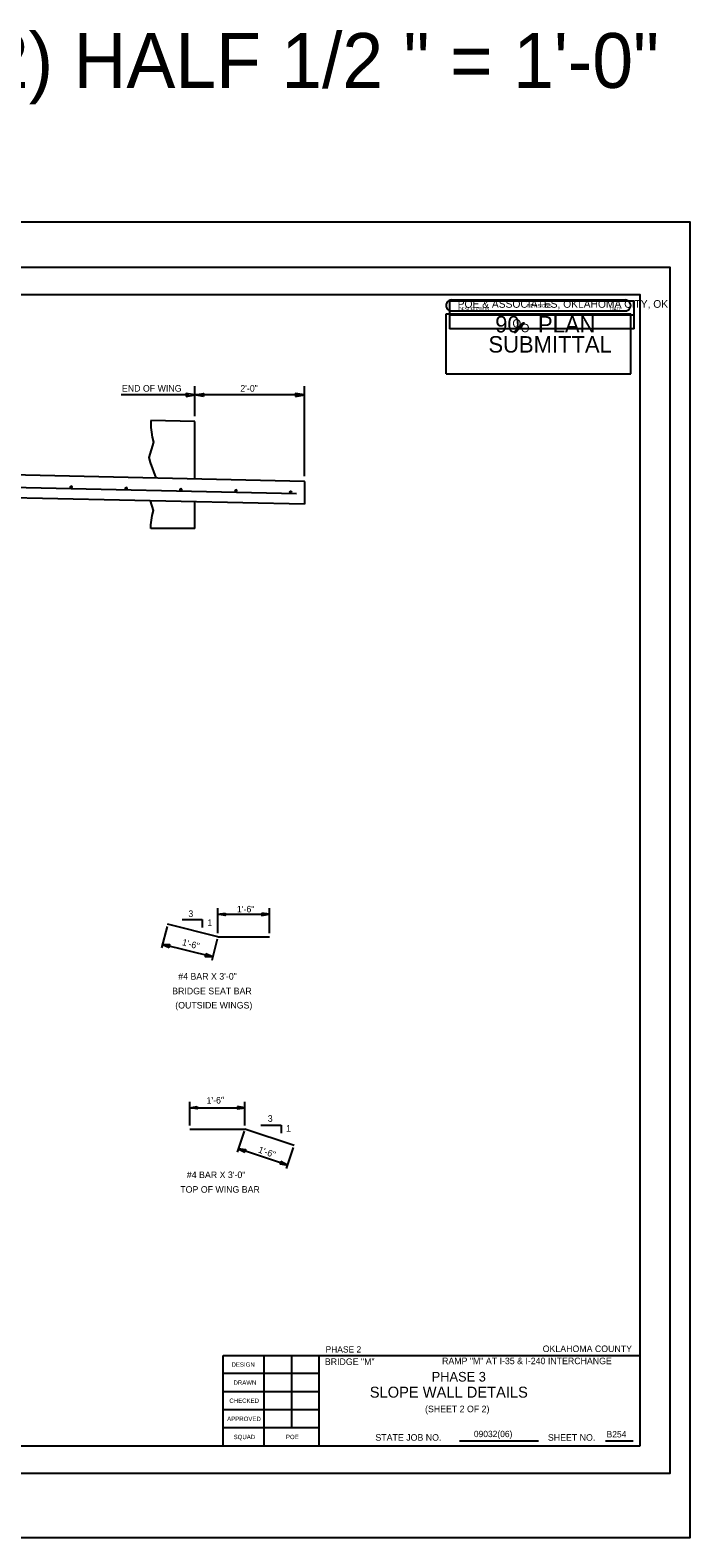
# Model space of a CAD drawing. Extents: x 570 to 2153298, y 726 to 139926.
# Drawn here: x 2153165.19 to 2153177.23, y 139597.62 to 139625.12 of the extents above; entities that cross this region are included whole.
import ezdxf

# ---------------------------------------------------------------- set-up
doc = ezdxf.new("R2010")
doc.units = 0
for name, color, linetype in [('4', 7, 'Continuous'), ('6', 7, 'Continuous'), ('Default', 7, 'Continuous'), ('PR_Bridge_Prof', 7, 'Continuous'), ('PR_Dimensions', 7, 'Continuous'), ('PR_JOINT', 7, 'Continuous'), ('PR_Reinforcing', 7, 'Continuous'), ('PR_SlopeWall', 7, 'Continuous'), ('S', 7, 'Continuous'), ('SHT_Plot_Shape_Full', 7, 'Continuous'), ('SHT_Plot_Shape_Half', 7, 'Continuous'), ('SHT_Sheet_Border', 7, 'Continuous'), ('SHT_Stamp_90_Submit', 7, 'Continuous'), ('SHT_Stamp_Rev_Block', 7, 'Continuous'), ('SHT_Standard_Sheet_Lines', 7, 'Continuous'), ('SHT_Standard_Sheet_Txt', 7, 'Continuous'), ('T', 7, 'Continuous'), ('T-Title', 7, 'Continuous')]:
    doc.layers.add(name, color=color, linetype=linetype)

# ---------------------------------------------------------------- blocks, each defined once
blk = doc.blocks.new('ARROWHD_15')
at = {"layer": 'Default'}
blk.add_lwpolyline([(0.0261, -0.0045), (0.0261, 0.0043), (-0.0004, -0.0001)], close=True, dxfattribs=at)

msp = doc.modelspace()

# ---------------------------------------------------------------- linework, layer by layer
at = {"layer": '4'}
for p, q in [((2153168.613, 139608.583), (2153167.699, 139608.813)), ((2153168.613, 139608.583), (2153169.555, 139608.583)), ((2153168.102, 139605.078), (2153169.111, 139605.078)), ((2153170.005, 139604.78), (2153169.111, 139605.078))]:
    msp.add_line(p, q, dxfattribs=at)
at = {"layer": '6'}
for p, q in [((2153168.196, 139618.079), (2153168.196, 139618.623)), ((2153170.195, 139616.986), (2153170.195, 139618.623)), ((2153168.084, 139618.465), (2153166.85, 139618.465)), ((2153170.195, 139618.465), (2153168.196, 139618.465)), ((2153168.613, 139608.65), (2153168.613, 139609.103)), ((2153168.613, 139608.995), (2153169.555, 139608.995)), ((2153169.555, 139608.65), (2153169.555, 139609.103)), ((2153167.689, 139608.773), (2153167.59, 139608.381)), ((2153167.962, 139608.896), (2153168.328, 139608.896)), ((2153168.328, 139608.896), (2153168.328, 139608.751)), ((2153168.52, 139608.216), (2153167.607, 139608.446)), ((2153168.603, 139608.543), (2153168.504, 139608.15)), ((2153168.102, 139605.145), (2153168.102, 139605.574)), ((2153168.102, 139605.466), (2153169.111, 139605.466)), ((2153169.111, 139605.145), (2153169.111, 139605.574)), ((2153169.402, 139605.147), (2153169.768, 139605.147)), ((2153169.768, 139605.147), (2153169.768, 139605.002)), ((2153169.098, 139605.039), (2153168.97, 139604.655)), ((2153169.885, 139604.421), (2153168.991, 139604.719)), ((2153169.992, 139604.741), (2153169.864, 139604.357))]:
    msp.add_line(p, q, dxfattribs=at)
for points in [[(2153168.036, 139618.439), (2153168.196, 139618.465), (2153168.036, 139618.492)], [(2153168.356, 139618.439), (2153168.196, 139618.465), (2153168.356, 139618.492)], [(2153170.035, 139618.439), (2153170.195, 139618.465), (2153170.035, 139618.492)], [(2153168.751, 139609.017), (2153168.751, 139608.972), (2153168.616, 139608.995)], [(2153169.416, 139609.017), (2153169.416, 139608.972), (2153169.551, 139608.995)], [(2153168.241, 139605.489), (2153168.241, 139605.444), (2153168.106, 139605.466)], [(2153168.973, 139605.489), (2153168.973, 139605.444), (2153169.107, 139605.466)]]:
    msp.add_lwpolyline(points, close=True, dxfattribs=at)
at = {"layer": 'PR_Bridge_Prof'}
for p, q in [((2153168.199, 139617.981), (2153167.394, 139617.999)), ((2153168.199, 139616.933), (2153168.199, 139617.981)), ((2153168.199, 139616.028), (2153168.199, 139616.516)), ((2153168.199, 139616.028), (2153167.391, 139616.027))]:
    msp.add_line(p, q, dxfattribs=at)
at = {"layer": 'PR_Dimensions'}
msp.add_line((2153170.198, 139616.888), (2153170.203, 139616.888), dxfattribs=at)
at = {"layer": 'PR_JOINT'}
for points in [[(2153167.394, 139617.999), (2153167.391, 139617.953), (2153167.394, 139617.87), (2153167.404, 139617.784), (2153167.419, 139617.696), (2153167.44, 139617.606), (2153167.357, 139617.323), (2153167.384, 139617.235), (2153167.482, 139616.951)], [(2153167.391, 139616.027), (2153167.394, 139616.094), (2153167.404, 139616.18), (2153167.419, 139616.268), (2153167.44, 139616.358), (2153167.388, 139616.537)]]:
    msp.add_lwpolyline(points, dxfattribs=at)
at = {"layer": 'PR_Reinforcing'}
msp.add_line((2153170.053, 139616.659), (2153162.812, 139616.822), dxfattribs=at)
for centre in [(2153165.941, 139616.785), (2153166.944, 139616.761), (2153167.941, 139616.738), (2153168.945, 139616.718), (2153169.943, 139616.693)]:
    msp.add_circle(centre, 0.0143, dxfattribs=at)
for centre, start, end in [((2153165.941, 139616.785), 356.6255, 176.6255), ((2153165.941, 139616.785), 176.6255, 356.6255), ((2153166.944, 139616.761), 356.6255, 176.6255), ((2153166.944, 139616.761), 176.6255, 356.6255), ((2153167.941, 139616.738), 356.6255, 176.6255), ((2153167.941, 139616.738), 176.6255, 356.6255), ((2153168.945, 139616.718), 356.6255, 176.6255), ((2153168.945, 139616.718), 176.6255, 356.6255), ((2153169.943, 139616.693), 356.6255, 176.6255), ((2153169.943, 139616.693), 176.6255, 356.6255)]:
    msp.add_arc(centre, 0.0143, start, end, dxfattribs=at)
at = {"layer": 'PR_SlopeWall'}
for p, q in [((2153170.198, 139616.888), (2153162.823, 139617.054)), ((2153170.198, 139616.471), (2153162.834, 139616.637)), ((2153170.198, 139616.888), (2153170.198, 139616.471))]:
    msp.add_line(p, q, dxfattribs=at)
at = {"layer": 'SHT_Plot_Shape_Full'}
msp.add_lwpolyline([(2153141.225, 139621.622), (2153177.225, 139621.622), (2153177.225, 139597.622), (2153141.225, 139597.622)], close=True, dxfattribs=at)
at = {"layer": 'SHT_Plot_Shape_Half'}
msp.add_lwpolyline([(2153142.863, 139620.797), (2153176.863, 139620.797), (2153176.863, 139598.797), (2153142.863, 139598.797)], close=True, dxfattribs=at)
at = {"layer": 'SHT_Sheet_Border'}
for p, q in [((2153168.713, 139599.297), (2153168.713, 139600.947)), ((2153168.713, 139600.947), (2153176.313, 139600.947)), ((2153170.463, 139599.297), (2153170.463, 139600.948))]:
    msp.add_line(p, q, dxfattribs=at)
msp.add_lwpolyline([(2153176.313, 139599.297), (2153144.813, 139599.297), (2153144.813, 139620.297), (2153176.313, 139620.297)], close=True, dxfattribs=at)
at = {"layer": 'SHT_Stamp_90_Submit'}
for p, q in [((2153172.78, 139619.947), (2153176.146, 139619.947)), ((2153172.78, 139618.848), (2153172.78, 139619.947)), ((2153172.88, 139620.197), (2153176.046, 139620.197)), ((2153172.88, 139619.997), (2153176.046, 139619.997)), ((2153176.146, 139618.848), (2153176.146, 139619.947)), ((2153174.023, 139619.609), (2153174.179, 139619.781)), ((2153174.041, 139619.609), (2153174.197, 139619.781)), ((2153174.046, 139619.609), (2153174.202, 139619.781)), ((2153174.054, 139619.609), (2153174.209, 139619.781)), ((2153174.179, 139619.781), (2153174.209, 139619.781)), ((2153174.023, 139619.609), (2153174.054, 139619.609)), ((2153172.78, 139618.848), (2153176.146, 139618.848))]:
    msp.add_line(p, q, dxfattribs=at)
for centre, start, end in [((2153172.88, 139620.097), 89.9952, 270), ((2153176.046, 139620.097), 270, 90.0048)]:
    msp.add_arc(centre, 0.1, start, end, dxfattribs=at)
at = {"layer": 'SHT_Stamp_Rev_Block'}
for p, q in [((2153172.844, 139620.173), (2153172.844, 139619.673)), ((2153176.209, 139620.173), (2153172.844, 139620.173)), ((2153176.209, 139619.673), (2153176.209, 139620.173)), ((2153176.209, 139619.923), (2153172.844, 139619.923)), ((2153176.209, 139619.673), (2153172.844, 139619.673))]:
    msp.add_line(p, q, dxfattribs=at)
at = {"layer": 'SHT_Standard_Sheet_Lines'}
for p, q in [((2153169.463, 139599.297), (2153169.463, 139600.948)), ((2153169.963, 139599.627), (2153169.963, 139600.948)), ((2153173.023, 139599.393), (2153174.464, 139599.393)), ((2153175.688, 139599.393), (2153176.191, 139599.393))]:
    msp.add_line(p, q, dxfattribs=at)
for points in [[(2153170.463, 139600.617), (2153168.713, 139600.617)], [(2153170.463, 139600.287), (2153168.713, 139600.287)], [(2153170.463, 139599.957), (2153168.713, 139599.957)], [(2153170.463, 139599.627), (2153168.713, 139599.627)]]:
    msp.add_lwpolyline(points, dxfattribs=at)

# ---------------------------------------------------------------- block references
at = {"layer": '6'}
for p, xscale, yscale, rotation in [((2153167.607, 139608.446), 5.094669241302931, 5.094669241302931, -14.135073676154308), ((2153168.52, 139608.216), 5.094669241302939, 5.094669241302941, 165.86492632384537), ((2153168.991, 139604.719), 5.094669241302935, 5.094669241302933, -18.425793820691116), ((2153169.883, 139604.421), 5.094669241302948, 5.094669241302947, 161.5742061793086)]:
    msp.add_blockref('ARROWHD_15', p, dxfattribs=dict(at, xscale=xscale, yscale=yscale, rotation=rotation))

# ---------------------------------------------------------------- texts
at = {"layer": 'Defpoints'}
msp.add_text('PHASE 3', height=0.175, dxfattribs=at).set_placement((2153172.516, 139600.473))
at = {"layer": 'S'}
msp.add_text('SCALE:  FULL 1" = 1\'-0" (SF=12) HALF 1/2 " = 1\'-0"', height=1.00003, dxfattribs=at).set_placement((2153145.825, 139624.065))
at = {"layer": 'SHT_Stamp_90_Submit'}
for s, height, p in [('POE & ASSOCIATES, OKLAHOMA CITY, OK.', 0.14, (2153172.99, 139620.055)), ('90   PLAN', 0.3, (2153173.675, 139619.605)), ('O', 0.153, (2153173.989, 139619.694)), ('O', 0.153, (2153174.141, 139619.609)), ('SUBMITTAL', 0.3, (2153173.551, 139619.238))]:
    msp.add_text(s, height=height, dxfattribs=at).set_placement(p)
at = {"layer": 'SHT_Stamp_Rev_Block'}
for s, height, p in [('DESCRIPTION', 0.05999, (2153173.004, 139620.001)), ('REVISIONS', 0.06, (2153174.252, 139620.061)), ('DATE', 0.06, (2153175.773, 139620.006))]:
    msp.add_text(s, height=height, dxfattribs=at).set_placement(p)
at = {"layer": 'SHT_Standard_Sheet_Txt'}
for s, height, p in [('DESIGN', 0.08, (2153168.865, 139600.743)), ('DRAWN', 0.08, (2153168.901, 139600.413)), ('CHECKED', 0.08, (2153168.826, 139600.083)), ('APPROVED', 0.08, (2153168.786, 139599.752)), ('SQUAD', 0.08, (2153168.904, 139599.422)), ('POE', 0.08, (2153169.858, 139599.422)), ('STATE JOB NO.', 0.12, (2153171.49, 139599.393)), ('SHEET NO. ', 0.12, (2153174.636, 139599.393))]:
    msp.add_text(s, height=height, dxfattribs=at).set_placement(p)
at = {"layer": 'T'}
for s, height, p in [('END OF WING', 0.12, (2153166.866, 139618.525)), ('2\'-0"', 0.12, (2153169.026, 139618.525)), ('3', 0.12, (2153168.078, 139608.944)), ('1\'-6"', 0.12, (2153168.964, 139609.028)), ('1', 0.12, (2153168.424, 139608.78)), ('#4 BAR X 3\'-0"', 0.12, (2153167.893, 139607.802)), ('BRIDGE SEAT BAR', 0.11979, (2153167.783, 139607.535)), ('(OUTSIDE WINGS)', 0.11979, (2153167.839, 139607.276)), ('3', 0.12, (2153169.527, 139605.21)), ('1', 0.12, (2153169.861, 139605.03)), ('#4 BAR X 3\'-0"', 0.12, (2153168.05, 139604.183)), ('TOP OF WING BAR', 0.11979, (2153167.931, 139603.916)), ('PHASE 2', 0.1152, (2153170.58, 139601.002)), ('OKLAHOMA COUNTY', 0.11979, (2153174.541, 139601.01)), ('BRIDGE "M" ', 0.12, (2153170.567, 139600.775)), ('RAMP "M" AT I-35 & I-240 INTERCHANGE', 0.11979, (2153172.706, 139600.789)), ('(SHEET 2 OF 2)', 0.11979, (2153172.395, 139599.913)), ('09032(06)', 0.1152, (2153173.286, 139599.459)), ('B254', 0.1152, (2153175.707, 139599.453))]:
    msp.add_text(s, height=height, dxfattribs=at).set_placement(p)
for rotation, p in [(345.1138, (2153167.954, 139608.433)), (1.5677, (2153168.411, 139605.537)), (340.8033, (2153169.342, 139604.652))]:
    msp.add_text('1\'-6"', height=0.12, rotation=rotation, dxfattribs=at).set_placement(p)
at = {"layer": 'T-Title'}
msp.add_text('SLOPE WALL DETAILS', height=0.2, dxfattribs=at).set_placement((2153171.387, 139600.179))

doc.saveas('drawing.dxf')
